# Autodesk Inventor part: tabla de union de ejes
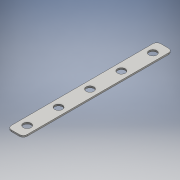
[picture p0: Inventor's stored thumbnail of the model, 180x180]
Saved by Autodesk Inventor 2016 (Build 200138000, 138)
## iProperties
Created: 2016-06
Part Number: tabla de union de ejes
Material: Genérico
Document SubType Name: Modeling
Designer: adm
Density: 1 g/cm^3
Appearance: Valor por defecto
Author: adm
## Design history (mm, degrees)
sketch "Boceto1"
  geometry: L1 (-20, -190)-(20, -190); L2 (20, -190)-(20, 190); L3 (20, 190)-(-20, 190); L4 (-20, 190)-(-20, -190); L5 (-20, -190)-(20, 190); L6 (20, -190)-(-20, 190); 1 further point
  constraints: 12 end point, 2 midpoint, 2 parallel, 1 horizontal, 1 perpendicular
  dimensions: "d0" = 40 distance of L2.end L3.end; "d1" = 380 distance of L1.end L2.end
extrude "Extrusión1" new body sketch "Boceto1" distance "d2" = 4; taper "d3" = 0 deg
fillet "Empalme1" dims "d4" = 10
fillet "Empalme2" dims "d5" = 10
sketch "Boceto2"
  geometry: L1 (10, 190)-(-10, 190) reference; L2 (-10, -190)-(10, -190) reference; C1 r 10 at (0, 160); C2 r 10 at (0, 80); C3 r 10 at (0, 0); C4 r 10 at (0, -80); C5 r 10 at (0, -160); 6 further points
  constraints: 5 centre point, 5 coincident
  dimensions: "d6" = 30 distance from line of point (0, 160) L1; "d11" = 30 distance from line of L2 point (0, -160); "d12" = 20 diameter of C1; "d13" = 20 diameter of C2; "d14" = 20 diameter of C3; "d15" = 20 diameter of C4; "d16" = 20 diameter of C5; "d19" = 80 distance of point (0, 80) point (0, 160); "d20" = 80 distance of point (0, 0) point (0, 80); "d21" = 80 distance of point (0, -80) point (0, 0)
extrude "Extrusión2" cut sketch "Boceto2" distance "d17" = 4; taper "d18" = 0 deg
node "Sólido1"
